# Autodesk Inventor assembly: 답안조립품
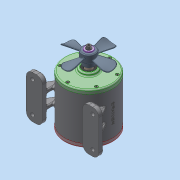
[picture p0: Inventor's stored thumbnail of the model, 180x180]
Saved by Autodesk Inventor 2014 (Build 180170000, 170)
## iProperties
Created: 2024-02
Part Number: 답안조립품
Document SubType Name: Assembly
Designer: dg
Mass: 3102.28 g
Surface Area: 2333.46 cm^2
Volume: 963.013 cm^3
Density: 3.22144 g/cm^3
Author: dg
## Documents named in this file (20)
- C:\Users\dg\Desktop\640204V1009\답안조립품.iam
- C:\Users\dg\Desktop\640204V1009\본체.ipt
- C:\Users\dg\Desktop\640204V1009\뒷커버.ipt
- C:\Users\dg\Desktop\640204V1009\오일 실 8 22 7.ipt
- C:\Users\dg\Desktop\640204V1009\베어링 608.ipt
- C:\Users\dg\Desktop\640204V1009\육각 소켓 머리 볼트 M4 x 12.ipt
- C:\Users\dg\Desktop\640204V1009\메인 기어 축.ipt
- C:\Users\dg\Desktop\640204V1009\서브 기어 축.ipt
- C:\Users\dg\Desktop\640204V1009\부시.ipt
- C:\Users\dg\Desktop\640204V1009\슬라이더.ipt
- C:\Users\dg\Desktop\640204V1009\가변스프링.ipt
- C:\Users\dg\Desktop\640204V1009\앞커버.ipt
- C:\Users\dg\Desktop\640204V1009\베어링 6903.ipt
- C:\Users\dg\Desktop\640204V1009\오일 실 17 30 8.ipt
- C:\Users\dg\Desktop\640204V1009\키 5 x 5 x 24.ipt
- C:\Users\dg\Desktop\640204V1009\팬날개.ipt
- 팬날개.ipt
- C:\Users\dg\Desktop\640204V1009\스프링 와셔 M6.ipt
- C:\Users\dg\Desktop\640204V1009\앤드 캡.ipt
- C:\Users\dg\Desktop\640204V1009\육각 소켓 머리 볼트 M6 x 12.ipt
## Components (1 placed, 1 different names)
1. 가변스프링:1
